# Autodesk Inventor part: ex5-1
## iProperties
Author: Administrator
Created: 2001-09
Part Number: ex5-1
Document SubType Name: Modeling
Designer: Administrator
Control State: 0
Master: False
Checked Out: False
PropertySet Name: Design Tracking Control
Length Units: 11272
Angle Units: 11279
Time Units: 11290
Mass Units: 11286
Shininess: 3
Angle Display Precision: 2
Document Length Units: 11272
Document Angle Units: 11286
Document Time Units: 11279
Document Mass Units: 11290
Document Length Units Precision: 3
Document Angle Units Precision: 2
Compacted: False
PropertySet Name: _Private Model Information
Density: 0.0
Volumn: 0.0
Area: 0.0
PropertySet Name: Model Information
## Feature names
1. Revolution1
